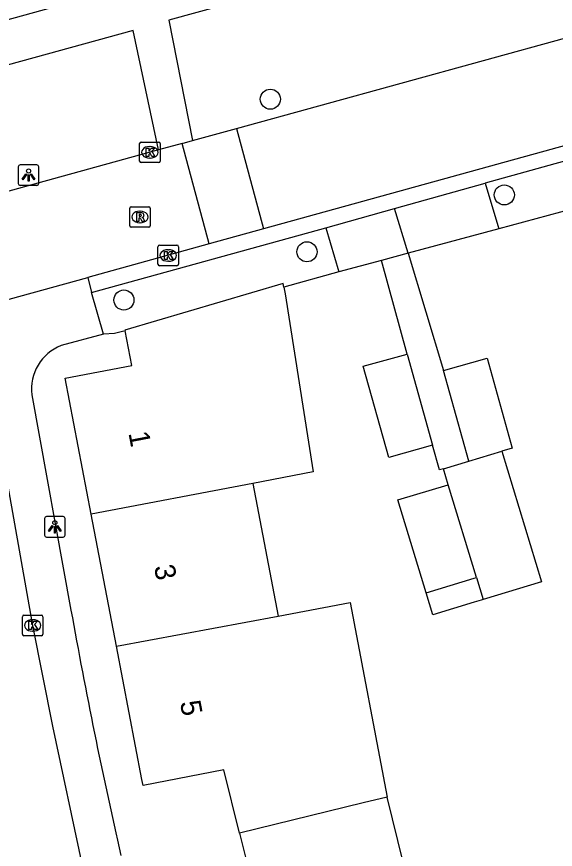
# Model space of a CAD drawing. Extents: x 159053 to 160041, y 380450 to 381422.
# Drawn here: x 159420.77 to 159447.01, y 380943.86 to 380984.43 of the extents above; entities that cross this region are included whole.
import ezdxf

# ---------------------------------------------------------------- set-up
doc = ezdxf.new("R2010")
doc.units = 0
for name, color, linetype in [('IMGEO_Boom', 7, 'Continuous'), ('IMGEO_Groenvoorziening', 7, 'Continuous'), ('IMGEO_Kolk', 7, 'Continuous'), ('IMGEO_Lichtpunt', 7, 'Continuous'), ('IMGEO_Pand', 7, 'Continuous'), ('IMGEO_Pand_nummerreeks', 7, 'Continuous'), ('IMGEO_Rijbaan_lokaal_open', 7, 'Continuous'), ('IMGEO_Rioolput', 7, 'Continuous'), ('IMGEO_Voetpad_open', 7, 'Continuous')]:
    doc.layers.add(name, color=color, linetype=linetype)

msp = doc.modelspace()

# ---------------------------------------------------------------- linework, layer by layer
at = {"layer": 'IMGEO_Boom'}
for centre in [(159433.129, 380980.41), (159444.528, 380975.745), (159434.914, 380972.974), (159425.996, 380970.626)]:
    msp.add_circle(centre, 0.489, dxfattribs=at)
at = {"layer": 'IMGEO_Groenvoorziening'}
for points in [[(159456.318, 380977.354), (159454.014, 380976.706), (159453.269, 380976.528), (159444.264, 380974.1)], [(159436.467, 380971.993), (159433.791, 380971.258)], [(159426.053, 380969.131), (159425.529, 380968.987), (159424.993, 380968.961)]]:
    msp.add_lwpolyline(points, dxfattribs=at)
at = {"layer": 'IMGEO_Kolk'}
for p, q in [((159426.759, 380977.396), (159426.759, 380978.248)), ((159426.834, 380978.322), (159427.686, 380978.322)), ((159427.76, 380978.248), (159427.76, 380977.396)), ((159427.247, 380978.102), (159427.272, 380978.102)), ((159427.27, 380977.542), (159427.245, 380977.542)), ((159427.686, 380977.322), (159426.834, 380977.322)), ((159427.653, 380972.37), (159427.653, 380973.222)), ((159427.728, 380973.296), (159428.58, 380973.296)), ((159428.141, 380973.076), (159428.166, 380973.076)), ((159428.654, 380973.222), (159428.654, 380972.37)), ((159428.58, 380972.296), (159427.728, 380972.296)), ((159428.164, 380972.516), (159428.139, 380972.516)), ((159421.05, 380954.347), (159421.05, 380955.199)), ((159421.125, 380955.273), (159421.977, 380955.273)), ((159422.051, 380955.199), (159422.051, 380954.347)), ((159421.538, 380955.053), (159421.563, 380955.053)), ((159421.561, 380954.493), (159421.536, 380954.493)), ((159421.977, 380954.273), (159421.125, 380954.273))]:
    msp.add_line(p, q, dxfattribs=at)
for points in [[(159426.759, 380977.396), (159426.759, 380978.248)], [(159426.834, 380978.322), (159427.686, 380978.322)], [(159427.76, 380978.248), (159427.76, 380977.396)], [(159427.08, 380978.022), (159427.203, 380978.022), (159427.203, 380977.871), (159427.333, 380978.022), (159427.497, 380978.022), (159427.351, 380977.871), (159427.504, 380977.622), (159427.352, 380977.622), (159427.267, 380977.786), (159427.203, 380977.719), (159427.203, 380977.622), (159427.08, 380977.622), (159427.08, 380978.022)], [(159427.686, 380977.322), (159426.834, 380977.322)], [(159427.653, 380972.37), (159427.653, 380973.222)], [(159427.728, 380973.296), (159428.58, 380973.296)], [(159427.974, 380972.996), (159428.097, 380972.996), (159428.097, 380972.845), (159428.227, 380972.996), (159428.391, 380972.996), (159428.245, 380972.845), (159428.398, 380972.596), (159428.246, 380972.596), (159428.161, 380972.76), (159428.097, 380972.693), (159428.097, 380972.596), (159427.974, 380972.596), (159427.974, 380972.996)], [(159428.654, 380973.222), (159428.654, 380972.37)], [(159428.58, 380972.296), (159427.728, 380972.296)], [(159421.05, 380954.347), (159421.05, 380955.199)], [(159421.125, 380955.273), (159421.977, 380955.273)], [(159422.051, 380955.199), (159422.051, 380954.347)], [(159421.371, 380954.973), (159421.494, 380954.973), (159421.494, 380954.822), (159421.624, 380954.973), (159421.788, 380954.973), (159421.642, 380954.822), (159421.795, 380954.573), (159421.643, 380954.573), (159421.558, 380954.737), (159421.494, 380954.67), (159421.494, 380954.573), (159421.371, 380954.573), (159421.371, 380954.973)], [(159421.977, 380954.273), (159421.125, 380954.273)]]:
    msp.add_lwpolyline(points, dxfattribs=at)
for centre, start, end in [((159426.836, 380978.246), 91.552, 178.448), ((159426.836, 380978.246), 91.552, 178.448), ((159427.684, 380978.246), 1.552, 88.448), ((159427.684, 380978.246), 1.552, 88.448), ((159426.836, 380977.398), 181.552, 268.448), ((159426.836, 380977.398), 181.552, 268.448), ((159427.684, 380977.398), 271.552, 358.448), ((159427.684, 380977.398), 271.552, 358.448), ((159427.73, 380973.22), 91.552, 178.448), ((159427.73, 380973.22), 91.552, 178.448), ((159428.578, 380973.22), 1.552, 88.448), ((159428.578, 380973.22), 1.552, 88.448), ((159427.73, 380972.372), 181.552, 268.448), ((159427.73, 380972.372), 181.552, 268.448), ((159428.578, 380972.372), 271.552, 358.448), ((159428.578, 380972.372), 271.552, 358.448), ((159421.127, 380955.197), 91.552, 178.448), ((159421.127, 380955.197), 91.552, 178.448), ((159421.975, 380955.197), 1.552, 88.448), ((159421.975, 380955.197), 1.552, 88.448), ((159421.127, 380954.349), 181.552, 268.448), ((159421.127, 380954.349), 181.552, 268.448), ((159421.975, 380954.349), 271.552, 358.448), ((159421.975, 380954.349), 271.552, 358.448)]:
    msp.add_arc(centre, 0.0765, start, end, dxfattribs=at)
for centre, major_axis, ratio, start_param, end_param in [((159427.246, 380977.822), (-0.387, 0.002), 0.722429, 4.712389, 7.853982), ((159427.271, 380977.822), (-0.39, 0.002), 0.717154, 1.570796, 4.712389), ((159428.14, 380972.796), (-0.387, 0.002), 0.722429, 4.712389, 7.853982), ((159428.165, 380972.796), (-0.39, 0.002), 0.717154, 1.570796, 4.712389), ((159421.537, 380954.773), (-0.387, 0.002), 0.722429, 4.712389, 7.853982), ((159421.562, 380954.773), (-0.39, 0.002), 0.717154, 1.570796, 4.712389)]:
    msp.add_ellipse(centre, major_axis=major_axis, ratio=ratio, start_param=start_param, end_param=end_param, dxfattribs=at)
at = {"layer": 'IMGEO_Lichtpunt'}
for p, q in [((159420.851, 380977.114), (159420.851, 380976.307)), ((159420.851, 380977.114), (159420.851, 380976.307)), ((159421.753, 380977.209), (159420.945, 380977.209)), ((159421.753, 380977.209), (159420.945, 380977.209)), ((159421.847, 380976.307), (159421.847, 380977.114)), ((159421.847, 380976.307), (159421.847, 380977.114)), ((159420.945, 380976.213), (159421.753, 380976.213)), ((159420.945, 380976.213), (159421.753, 380976.213)), ((159422.13, 380959.978), (159422.13, 380959.171)), ((159422.13, 380959.978), (159422.13, 380959.171)), ((159423.032, 380960.073), (159422.224, 380960.073)), ((159423.032, 380960.073), (159422.224, 380960.073)), ((159423.126, 380959.171), (159423.126, 380959.978)), ((159423.126, 380959.171), (159423.126, 380959.978)), ((159422.224, 380959.077), (159423.032, 380959.077)), ((159422.224, 380959.077), (159423.032, 380959.077))]:
    msp.add_line(p, q, dxfattribs=at)
for points in [[(159421.225, 380976.778), (159421.264, 380976.75), (159421.076, 380976.488), (159421.038, 380976.515), (159421.225, 380976.778)], [(159421.327, 380976.73), (159421.374, 380976.73), (159421.374, 380976.408), (159421.327, 380976.408), (159421.327, 380976.73)], [(159421.437, 380976.75), (159421.475, 380976.777), (159421.662, 380976.515), (159421.623, 380976.487), (159421.437, 380976.75)], [(159422.504, 380959.642), (159422.543, 380959.614), (159422.355, 380959.352), (159422.317, 380959.379), (159422.504, 380959.642)], [(159422.606, 380959.594), (159422.653, 380959.594), (159422.653, 380959.272), (159422.606, 380959.272), (159422.606, 380959.594)], [(159422.716, 380959.614), (159422.754, 380959.641), (159422.941, 380959.379), (159422.902, 380959.351), (159422.716, 380959.614)]]:
    msp.add_lwpolyline(points, dxfattribs=at)
for centre in [(159421.35, 380976.912), (159422.629, 380959.776)]:
    msp.add_circle(centre, 0.0994, dxfattribs=at)
for centre, start, end in [((159420.945, 380977.114), 90, 180), ((159420.945, 380977.114), 90, 180), ((159421.753, 380977.114), 0, 90), ((159421.753, 380977.114), 0, 90), ((159420.945, 380976.307), 180, 270), ((159420.945, 380976.307), 180, 270), ((159421.753, 380976.307), 270, 0), ((159421.753, 380976.307), 270, 360), ((159422.224, 380959.978), 90, 180), ((159422.224, 380959.978), 90, 180), ((159423.032, 380959.978), 0, 90), ((159423.032, 380959.978), 0, 90), ((159422.224, 380959.171), 180, 270), ((159422.224, 380959.171), 180, 270), ((159423.032, 380959.171), 270, 0), ((159423.032, 380959.171), 270, 360)]:
    msp.add_arc(centre, 0.0946, start, end, dxfattribs=at)
at = {"layer": 'IMGEO_Pand'}
for points in [[(159433.791, 380971.258), (159433.758, 380971.429), (159426.047, 380969.158), (159426.053, 380969.131)], [(159433.791, 380971.258), (159433.855, 380970.923), (159435.224, 380962.252), (159432.277, 380961.693)], [(159424.403, 380960.196), (159423.135, 380966.819), (159426.376, 380967.439), (159426.053, 380969.131)], [(159441.027, 380963.554), (159438.898, 380962.959), (159437.659, 380967.4), (159439.788, 380967.995)], [(159439.788, 380967.995), (159441.027, 380963.554)], [(159441.572, 380967.194), (159443.699, 380967.787), (159444.919, 380963.413), (159444.411, 380963.265)], [(159442.804, 380962.777), (159441.572, 380967.194)], [(159442.804, 380962.777), (159444.411, 380963.265)], [(159444.411, 380963.265), (159446.342, 380956.903), (159443.497, 380956.04)], [(159441.567, 380962.402), (159442.804, 380962.777)], [(159441.801, 380961.63), (159441.567, 380962.402)], [(159432.277, 380961.693), (159424.403, 380960.196)], [(159432.277, 380961.693), (159433.503, 380955.231)], [(159440.714, 380956.368), (159439.343, 380960.884), (159441.801, 380961.63)], [(159443.172, 380957.114), (159441.801, 380961.63)], [(159425.634, 380953.759), (159424.403, 380960.196)], [(159440.714, 380956.368), (159443.067, 380957.082), (159443.172, 380957.114)], [(159443.172, 380957.114), (159443.497, 380956.04)], [(159443.497, 380956.04), (159443.397, 380956.01), (159443.063, 380955.908), (159441.039, 380955.294), (159440.714, 380956.368)], [(159433.503, 380955.231), (159437.023, 380955.889), (159438.82, 380946.412)], [(159425.634, 380953.759), (159433.503, 380955.231)], [(159431.627, 380944.647), (159430.861, 380947.731), (159426.932, 380946.979), (159426.876, 380947.274), (159425.634, 380953.759)], [(159438.82, 380946.412), (159437.66, 380946.128), (159431.627, 380944.647)], [(159438.223, 380936.165), (159441.124, 380937.032), (159438.82, 380946.412)], [(159431.627, 380944.647), (159432.417, 380941.468), (159428.589, 380940.306), (159428.676, 380940.019), (159430.541, 380933.871)]]:
    msp.add_lwpolyline(points, dxfattribs=at)
at = {"layer": 'IMGEO_Rijbaan_lokaal_open'}
for points in [[(159431.485, 380978.987), (159447.525, 380983.393), (159449.011, 380983.736)], [(159455.382, 380980.342), (159448.97, 380978.562), (159432.803, 380974.092)], [(159429.341, 380978.394), (159431.485, 380978.987)], [(159431.485, 380978.987), (159432.803, 380974.092)], [(159428.84, 380978.256), (159427.679, 380977.936)], [(159428.84, 380978.256), (159429.341, 380978.394)], [(159430.149, 380973.358), (159428.84, 380978.256)], [(159427.679, 380977.936), (159407.199, 380972.295)], [(159432.803, 380974.092), (159430.149, 380973.358)], [(159430.149, 380973.358), (159424.234, 380971.723)], [(159420.412, 380970.666), (159424.234, 380971.723)], [(159419.726, 380964.951), (159421.546, 380954.773), (159422.519, 380949.866), (159423.957, 380943.077)]]:
    msp.add_lwpolyline(points, dxfattribs=at)
at = {"layer": 'IMGEO_Rioolput'}
for p, q in [((159426.278, 380974.246), (159426.278, 380975.098)), ((159426.353, 380975.172), (159427.205, 380975.172)), ((159427.279, 380975.098), (159427.279, 380974.246)), ((159426.766, 380974.952), (159426.791, 380974.952)), ((159426.789, 380974.392), (159426.764, 380974.392)), ((159427.205, 380974.172), (159426.353, 380974.172))]:
    msp.add_line(p, q, dxfattribs=at)
for points in [[(159426.278, 380974.246), (159426.278, 380975.098)], [(159426.353, 380975.172), (159427.205, 380975.172)], [(159427.279, 380975.098), (159427.279, 380974.246)], [(159426.867, 380974.87), (159426.615, 380974.872), (159426.615, 380974.472)], [(159426.615, 380974.472), (159426.739, 380974.472), (159426.739, 380974.634), (159426.75, 380974.634)], [(159426.793, 380974.791), (159426.739, 380974.791), (159426.739, 380974.71)], [(159426.739, 380974.71), (159426.791, 380974.71)], [(159426.797, 380974.605), (159426.868, 380974.472), (159427.008, 380974.472), (159426.943, 380974.598)], [(159427.205, 380974.172), (159426.353, 380974.172)]]:
    msp.add_lwpolyline(points, dxfattribs=at)
for centre, radius, start, end in [((159426.355, 380975.096), 0.0765, 91.552, 178.448), ((159426.355, 380975.096), 0.0765, 91.552, 178.448), ((159427.203, 380975.096), 0.0765, 1.552, 88.448), ((159427.203, 380975.096), 0.0765, 1.552, 88.448), ((159426.749, 380974.581), 0.0533, 26.0293, 88.6989), ((159426.775, 380974.899), 0.19, 274.7715, 282.9687), ((159426.799, 380974.695), 0.0964, 77.0061, 93.1865), ((159426.813, 380974.752), 0.0378, 276.6634, 79.6772), ((159426.866, 380974.76), 0.109, 350.3612, 89.416), ((159426.864, 380974.76), 0.112, 277.5842, 350.9817), ((159426.848, 380974.545), 0.108, 29.5134, 73.7905), ((159426.355, 380974.248), 0.0765, 181.552, 268.448), ((159426.355, 380974.248), 0.0765, 181.552, 268.448), ((159427.203, 380974.248), 0.0765, 271.552, 358.448), ((159427.203, 380974.248), 0.0765, 271.552, 358.448)]:
    msp.add_arc(centre, radius, start, end, dxfattribs=at)
for centre, major_axis, ratio, start_param, end_param in [((159426.765, 380974.672), (-0.387, 0.002), 0.722429, 4.712389, 7.853982), ((159426.79, 380974.672), (-0.39, 0.002), 0.717154, 1.570796, 4.712389)]:
    msp.add_ellipse(centre, major_axis=major_axis, ratio=ratio, start_param=start_param, end_param=end_param, dxfattribs=at)
at = {"layer": 'IMGEO_Voetpad_open'}
for points in [[(159449.011, 380983.736), (159448.118, 380989.715), (159447.176, 380989.466), (159428.187, 380984.259), (159429.341, 380978.394)], [(159405.022, 380980.072), (159426.077, 380985.889), (159425.664, 380988.567)], [(159427.679, 380977.936), (159426.442, 380983.759), (159399.81, 380976.439)], [(159455.6, 380979.643), (159443.602, 380976.314)], [(159439.186, 380975.088), (159443.602, 380976.314)], [(159443.602, 380976.314), (159444.264, 380974.1)], [(159435.826, 380974.138), (159439.186, 380975.088)], [(159439.838, 380972.906), (159439.186, 380975.088)], [(159424.414, 380971), (159435.826, 380974.138)], [(159435.826, 380974.138), (159436.467, 380971.993)], [(159444.264, 380974.1), (159439.838, 380972.906)], [(159438.552, 380972.558), (159436.467, 380971.993)], [(159439.838, 380972.906), (159438.552, 380972.558)], [(159439.788, 380967.995), (159438.552, 380972.558)], [(159439.838, 380972.906), (159441.572, 380967.194)], [(159424.234, 380971.723), (159424.414, 380971)], [(159424.993, 380968.961), (159424.414, 380971)], [(159424.993, 380968.961), (159422.944, 380968.402)], [(159421.509, 380966.004), (159423.417, 380955.517)], [(159441.567, 380962.402), (159441.364, 380962.345), (159441.027, 380963.554)]]:
    msp.add_lwpolyline(points, dxfattribs=at)
for centre, radius, start, end in [((159423.748, 380966.293), 2.257, 110.8632, 187.3429), ((159643.326, 380995.404), 234.129, 188.67315, 200.59863), ((159680.029, 381001.49), 260.697, 190.15695, 192.83868)]:
    msp.add_arc(centre, radius, start, end, dxfattribs=at)

# ---------------------------------------------------------------- texts
at = {"layer": 'IMGEO_Pand_nummerreeks'}
for s, p in [('1', (159426.213, 380964.144)), ('3', (159427.457, 380957.643)), ('5', (159428.722, 380951.03))]:
    msp.add_text(s, height=1, rotation=280.8343, dxfattribs=at).set_placement(p)

doc.saveas('drawing.dxf')
